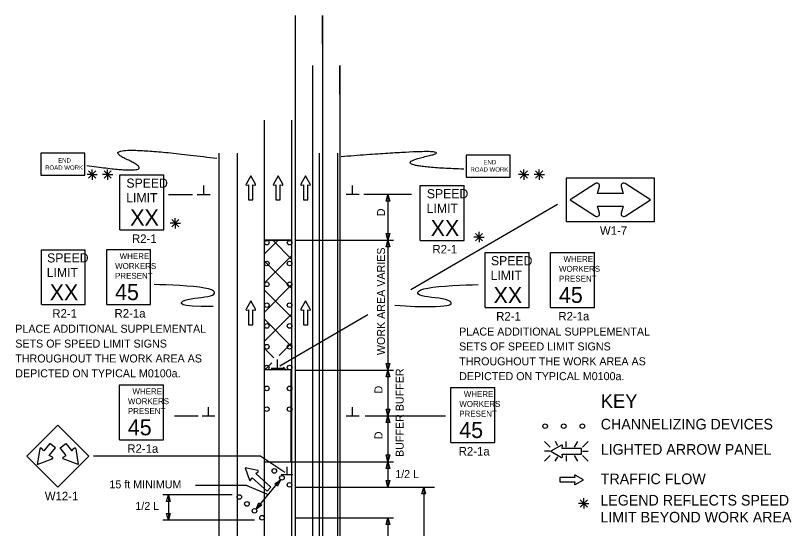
# Model space of a CAD drawing. Extents: x 16729 to 18482, y 7002 to 8333.
# Drawn here: x 16736 to 17415, y 7884 to 8333 of the extents above; entities that cross this region are included whole.
import ezdxf

# ---------------------------------------------------------------- set-up
doc = ezdxf.new("R2010")
doc.units = 0
for name, color, linetype in [('ALI_LEGAL_EX', 7, 'Continuous'), ('MT_SCRATCH_LEVEL_E', 7, 'Continuous'), ('PAVT_EDGE_EX', 7, 'Continuous'), ('TRAFFIC_SIGNS_PR', 7, 'Continuous'), ('TYPICAL_TEXT_DIMEN_EX', 7, 'Continuous'), ('TYPICAL_TEXT_DIMEN_PR', 7, 'Continuous')]:
    doc.layers.add(name, color=color, linetype=linetype)

msp = doc.modelspace()

# ---------------------------------------------------------------- linework, layer by layer
at = {"layer": 'ALI_LEGAL_EX'}
for p, q in [((16980.68, 8333.08), (16980.68, 7514.94)), ((17004.68, 8333.08), (17004.68, 7514.94)), ((16995.95, 8289.26), (16995.95, 7471.12)), ((17019.95, 8289.26), (17019.95, 7471.12)), ((16953.87, 7620.35), (16953.87, 8241.48)), ((16977.87, 7620.35), (16977.87, 8241.48))]:
    msp.add_line(p, q, dxfattribs=at)
for points in [[(17004.68, 8308.08), (17004.68, 8333.08)], [(17019.95, 8264.26), (17019.95, 8289.26)], [(16953.87, 8175.35), (16953.87, 8200.34)], [(16977.87, 8175.35), (16977.87, 8200.34)], [(16953.87, 8075.35), (16953.87, 8100.35)], [(16977.87, 8075.35), (16977.87, 8100.35)]]:
    msp.add_lwpolyline(points, dxfattribs=at)
at = {"layer": 'MT_SCRATCH_LEVEL_E'}
for p, q in [((16941.87, 8192.71), (16937.75, 8185.47)), ((16946.01, 8185.47), (16941.87, 8192.71)), ((16965.77, 8192.71), (16961.66, 8185.47)), ((16969.92, 8185.47), (16965.77, 8192.71)), ((16989.82, 8192.71), (16985.71, 8185.47)), ((16993.97, 8185.47), (16989.82, 8192.71)), ((16938.24, 8184.79), (16940.01, 8185.1)), ((16940.01, 8185.1), (16940.01, 8171.85)), ((16943.76, 8171.85), (16943.76, 8185.1)), ((16943.76, 8185.1), (16945.53, 8184.79)), ((16962.14, 8184.79), (16963.92, 8185.1)), ((16963.92, 8185.1), (16963.92, 8171.85)), ((16967.66, 8171.85), (16967.66, 8185.1)), ((16967.66, 8185.1), (16969.44, 8184.79)), ((16986.19, 8184.79), (16987.97, 8185.1)), ((16987.97, 8185.1), (16987.97, 8171.85)), ((16991.71, 8171.85), (16991.71, 8185.1)), ((16991.71, 8185.1), (16993.49, 8184.79)), ((16940.01, 8171.85), (16943.76, 8171.85)), ((16963.92, 8171.85), (16967.66, 8171.85)), ((16987.97, 8171.85), (16991.71, 8171.85)), ((16941.87, 8083.36), (16937.75, 8076.12)), ((16946.01, 8076.12), (16941.87, 8083.36)), ((16989.82, 8083.36), (16985.71, 8076.12)), ((16993.97, 8076.12), (16989.82, 8083.36)), ((16938.24, 8075.44), (16940.01, 8075.75)), ((16940.01, 8075.75), (16940.01, 8062.5)), ((16943.76, 8062.5), (16943.76, 8075.75)), ((16943.76, 8075.75), (16945.53, 8075.44)), ((16986.19, 8075.44), (16987.97, 8075.75)), ((16987.97, 8075.75), (16987.97, 8062.5)), ((16991.71, 8062.5), (16991.71, 8075.75)), ((16991.71, 8075.75), (16993.49, 8075.44)), ((16940.01, 8062.5), (16943.76, 8062.5)), ((16987.97, 8062.5), (16991.71, 8062.5)), ((16948, 7934.97), (16937.12, 7937.29)), ((16937.12, 7937.29), (16940.66, 7926.77)), ((16946.36, 7932.4), (16948.25, 7933.89)), ((16959.53, 7920.61), (16946.36, 7932.4)), ((17225.12, 7930.63), (17225.43, 7928.85)), ((17233.04, 7927), (17225.8, 7931.11)), ((16941.76, 7926.64), (16943.03, 7928.68)), ((16943.03, 7928.68), (16956.2, 7916.89)), ((17225.43, 7928.85), (17212.17, 7928.85)), ((17212.17, 7928.85), (17212.17, 7925.11)), ((17212.17, 7925.11), (17225.43, 7925.11)), ((17225.43, 7925.11), (17225.12, 7923.33)), ((17225.8, 7922.85), (17233.04, 7927)), ((16956.2, 7916.89), (16959.53, 7920.61))]:
    msp.add_line(p, q, dxfattribs=at)
for centre, radius, start, end in [((16938.16, 8185.25), 0.463, 150.42484, 279.96381), ((16945.6, 8185.25), 0.463, 260.03619, 29.77312), ((16962.07, 8185.25), 0.463, 150.42484, 279.96381), ((16969.51, 8185.25), 0.463, 260.03619, 29.77312), ((16986.12, 8185.25), 0.463, 150.42484, 279.96381), ((16993.56, 8185.25), 0.463, 260.03619, 29.77312), ((16938.16, 8075.9), 0.463, 150.42484, 279.96381), ((16945.6, 8075.9), 0.463, 260.03619, 29.77312), ((16986.12, 8075.9), 0.463, 150.42484, 279.96381), ((16993.56, 8075.9), 0.463, 260.03619, 29.77312), ((16947.86, 7934.37), 0.617, 308.20022, 77.93715), ((17225.58, 7930.7), 0.463, 60.42484, 189.96381), ((16941.24, 7926.97), 0.617, 198.58887, 328.12784), ((17225.58, 7923.26), 0.463, 170.03619, 299.77312)]:
    msp.add_arc(centre, radius, start, end, dxfattribs=at)
at = {"layer": 'PAVT_EDGE_EX'}
for p, q in [((16913.87, 8212.75), (16913.87, 7553.94)), ((16929.87, 8212.75), (16929.87, 7553.94)), ((17001.87, 8212.75), (17001.87, 7553.94)), ((17017.87, 8212.75), (17017.87, 7553.94)), ((16977.87, 8136.53), (16953.87, 8136.53)), ((16953.87, 8136.53), (16977.87, 8136.53)), ((16953.87, 8136.53), (16977.87, 8136.53)), ((16953.87, 8124.62), (16965.77, 8136.53)), ((16977.87, 8119.72), (16961.06, 8136.53)), ((16953.87, 8099.17), (16977.87, 8123.17)), ((16977.87, 8094.26), (16953.87, 8118.26)), ((16953.87, 8073.71), (16977.87, 8097.71)), ((16977.87, 8068.81), (16953.87, 8092.81)), ((16953.87, 8048.26), (16977.87, 8072.26)), ((16977.87, 8043.35), (16953.87, 8067.35)), ((16966.65, 8035.59), (16977.87, 8046.8)), ((16962.09, 8033.67), (16953.87, 8041.89)), ((16953.87, 8022.8), (16960.46, 8029.4)), ((16972.96, 8022.8), (16970.42, 8025.34))]:
    msp.add_line(p, q, dxfattribs=at)
msp.add_lwpolyline([(16977.33, 8023.14), (16953.49, 8023.14), (16953.49, 7942.8), (16977.33, 7942.8)], close=True, dxfattribs=at)
at = {"layer": 'TRAFFIC_SIGNS_PR'}
for p, q in [((16827.3, 8193.63), (16865.7, 8193.63)), ((16827.3, 8145.63), (16827.3, 8193.63)), ((16865.7, 8145.63), (16865.7, 8193.63)), ((17090.18, 8184.37), (17128.58, 8184.37)), ((17090.18, 8136.37), (17090.18, 8184.37)), ((17128.58, 8136.37), (17128.58, 8184.37)), ((16827.3, 8145.63), (16865.7, 8145.63)), ((17090.18, 8136.37), (17128.58, 8136.37)), ((16758.65, 8128.21), (16797.05, 8128.21)), ((16758.65, 8080.21), (16758.65, 8128.21)), ((16797.05, 8080.21), (16797.05, 8128.21)), ((16815.85, 8128.3), (16854.25, 8128.3)), ((16815.85, 8080.3), (16815.85, 8128.3)), ((16854.25, 8080.3), (16854.25, 8128.3)), ((17147.01, 8125.72), (17185.41, 8125.72)), ((17147.01, 8077.72), (17147.01, 8125.72)), ((17185.41, 8077.72), (17185.41, 8125.72)), ((17204.21, 8125.8), (17242.61, 8125.8)), ((17204.21, 8077.8), (17204.21, 8125.8)), ((17242.61, 8077.8), (17242.61, 8125.8)), ((16758.65, 8080.21), (16797.05, 8080.21)), ((16815.85, 8080.3), (16854.25, 8080.3)), ((17147.01, 8077.72), (17185.41, 8077.72)), ((17204.21, 8077.8), (17242.61, 8077.8)), ((16827.03, 8010.02), (16865.43, 8010.02)), ((16827.03, 7962.02), (16827.03, 8010.02)), ((16865.43, 7962.02), (16865.43, 8010.02)), ((17116.98, 8007.65), (17155.38, 8007.65)), ((17116.98, 7959.65), (17116.98, 8007.65)), ((17155.38, 7959.65), (17155.38, 8007.65)), ((16773.02, 7974.75), (16745.87, 7947.59)), ((16800.17, 7947.59), (16773.02, 7974.75)), ((16827.03, 7962.02), (16865.43, 7962.02)), ((17116.98, 7959.65), (17155.38, 7959.65)), ((17198.85, 7960.38), (17203.79, 7955.45)), ((17210.62, 7956.56), (17208.41, 7960.38)), ((17217.94, 7955.45), (17217.94, 7960.38)), ((17225.17, 7955.45), (17228.02, 7960.38)), ((17232.08, 7955.45), (17237.02, 7960.38)), ((16758.11, 7953.99), (16757.34, 7954.12)), ((17203.79, 7951.89), (17198.85, 7951.89)), ((17232.08, 7951.89), (17237.02, 7951.89)), ((16745.87, 7947.59), (16773.02, 7920.44)), ((16767.92, 7946.12), (16768.21, 7945.37)), ((16773.02, 7920.44), (16800.17, 7947.59)), ((17198.85, 7943.4), (17203.79, 7948.34)), ((17208.36, 7943.4), (17210.48, 7947.06)), ((17217.94, 7948.34), (17217.94, 7943.4)), ((17228.06, 7943.4), (17225.22, 7948.34)), ((17232.08, 7948.34), (17237.02, 7943.4))]:
    msp.add_line(p, q, dxfattribs=at)
for points in [[(16758.34, 8193.37), (16796.74, 8193.37), (16796.74, 8212.57), (16758.34, 8212.57)], [(17130.46, 8191.77), (17168.85, 8191.77), (17168.85, 8210.97), (17130.46, 8210.97)], [(17294.85, 8152.68), (17218.05, 8152.68), (17218.05, 8191.08), (17294.85, 8191.08)]]:
    msp.add_lwpolyline(points, close=True, dxfattribs=at)
for points in [[(17243.57, 8186.08), (17221.25, 8171.88), (17243.57, 8157.67)], [(17265.97, 8183.6), (17267.65, 8177.48), (17245.26, 8177.48), (17246.93, 8183.6)], [(17269.33, 8157.68), (17291.65, 8171.88), (17269.33, 8186.08)], [(17246.93, 8160.16), (17245.26, 8166.28), (17267.65, 8166.28), (17265.97, 8160.16)], [(16768.31, 7946.82), (16765.63, 7948.25), (16770.9, 7954.8), (16765.98, 7958.77), (16760.7, 7952.21), (16758.7, 7954.51)], [(16777.74, 7946.82), (16780.41, 7948.25), (16775.14, 7954.8), (16780.06, 7958.77), (16785.34, 7952.21), (16787.35, 7954.51)], [(17213.86, 7957.17), (17204.57, 7951.89), (17213.87, 7946.57)], [(16757.34, 7954.12), (16755.08, 7940.23), (16768.21, 7945.37)], [(16788.71, 7954.12), (16790.96, 7940.23), (16777.83, 7945.37)], [(17214.74, 7947.2), (17214.34, 7949.47), (17231.35, 7949.47), (17231.35, 7954.27), (17214.34, 7954.27), (17214.74, 7956.55)]]:
    msp.add_lwpolyline(points, dxfattribs=at)
for centre in [(16955.97, 8134.41), (16975.84, 8134.41), (16955.97, 8116.19), (16975.84, 8116.19), (16955.97, 8097.98), (16975.84, 8097.98), (16955.97, 8079.76), (16975.84, 8079.76), (16955.97, 8061.55), (16975.84, 8061.55), (16955.97, 8043.33), (16975.84, 8043.33), (16955.97, 8025.12), (16975.84, 8025.12), (16955.97, 8006.91), (16975.84, 8006.91), (16955.85, 7988.7), (16975.84, 7988.69), (17199.42, 7973.92), (17215.72, 7973.92), (17232.02, 7973.92), (16962.5, 7934.71), (16969.15, 7928.65), (16975.8, 7922.58), (16931.86, 7911.95), (16938.51, 7905.88), (16945.16, 7899.82), (16951.8, 7893.75), (16951.8, 7893.75)]:
    msp.add_circle(centre, 2, dxfattribs=at)
for centre, radius, start, end in [((17244.77, 8184.19), 2.24, 344.67308, 122.46963), ((17268.13, 8184.19), 2.24, 57.53038, 195.32692), ((17244.77, 8159.57), 2.24, 237.53038, 15.32692), ((17268.13, 8159.57), 2.24, 164.69282, 302.45235), ((17214.15, 7956.65), 0.598, 350.73078, 118.89165), ((16758.11, 7953.98), 0.786, 41.8659, 170.0393), ((16787.93, 7953.98), 0.786, 9.9607, 138.1341), ((16767.92, 7946.12), 0.8, 291.40774, 61.17916), ((16778.12, 7946.12), 0.8, 118.82084, 248.59226), ((17214.15, 7947.1), 0.597, 241.48329, 9.95933)]:
    msp.add_arc(centre, radius, start, end, dxfattribs=at)
for points in [[(16798.34, 8201.97), (16866.67, 8191.88), (16799.95, 8222.7), (16912.21, 8208.18)], [(17128.36, 8198.71), (17056.34, 8201), (17132.86, 8218.41), (17020.93, 8209.49)]]:
    msp.add_open_spline(points, degree=2, dxfattribs=at)
at = {"layer": 'TYPICAL_TEXT_DIMEN_PR'}
for p, q in [((16799.98, 8197.15), (16806.35, 8190.77)), ((16806.35, 8197.15), (16799.98, 8190.77)), ((16803.16, 8193.96), (16803.16, 8198.41)), ((16813.48, 8197.15), (16819.86, 8190.77)), ((16819.86, 8197.15), (16813.48, 8190.77)), ((16816.67, 8193.96), (16816.67, 8198.41)), ((17183.98, 8197.08), (17177.6, 8190.7)), ((17177.61, 8197.08), (17183.98, 8190.7)), ((17180.79, 8193.89), (17180.79, 8198.35)), ((17191.11, 8197.08), (17197.49, 8190.7)), ((17197.49, 8197.08), (17191.11, 8190.7)), ((17194.3, 8193.89), (17194.3, 8198.35)), ((16803.16, 8193.96), (16798.63, 8193.96)), ((16803.16, 8193.96), (16806.35, 8193.96)), ((16803.16, 8193.96), (16807.64, 8193.96)), ((16803.16, 8193.96), (16803.16, 8189.46)), ((16816.67, 8193.96), (16812.14, 8193.96)), ((16816.67, 8193.96), (16819.86, 8193.96)), ((16816.67, 8193.96), (16821.15, 8193.96)), ((16816.67, 8193.96), (16816.67, 8189.46)), ((17180.79, 8193.89), (17176.26, 8193.89)), ((17180.79, 8193.89), (17183.98, 8193.89)), ((17180.79, 8193.89), (17185.27, 8193.89)), ((17180.79, 8193.89), (17180.79, 8189.39)), ((17194.3, 8193.89), (17189.77, 8193.89)), ((17194.3, 8193.89), (17197.49, 8193.89)), ((17194.3, 8193.89), (17198.78, 8193.89)), ((17194.3, 8193.89), (17194.3, 8189.39)), ((16900.74, 8176.53), (16900.74, 8184.31)), ((16900.74, 8176.53), (16900.74, 8184.31)), ((17030.99, 8176.53), (17030.99, 8184.31)), ((16869.89, 8176.53), (16890.87, 8176.53)), ((16878.29, 8176.53), (16890.87, 8176.53)), ((16895.12, 8176.53), (16906.37, 8176.53)), ((16895.12, 8176.53), (16906.37, 8176.53)), ((17036.62, 8176.53), (17025.37, 8176.53)), ((17082.51, 8176.53), (17040.87, 8176.53)), ((17060.3, 8170.66), (17061.87, 8176.53)), ((17061.87, 8176.53), (17063.44, 8170.66)), ((17061.87, 8176.53), (17061.87, 8136.53)), ((17061.87, 8170.66), (17060.3, 8170.66)), ((17063.44, 8170.66), (17061.87, 8170.66)), ((17081.82, 8093.32), (17210.29, 8168.01)), ((16872.69, 8154.61), (16879.06, 8148.23)), ((16879.06, 8154.61), (16872.69, 8148.23)), ((16875.87, 8151.42), (16875.87, 8155.88)), ((16875.87, 8151.42), (16871.34, 8151.42)), ((16875.87, 8151.42), (16879.06, 8151.42)), ((16875.87, 8151.42), (16880.35, 8151.42)), ((16875.87, 8151.42), (16875.87, 8146.92)), ((17061.87, 8136.53), (17060.3, 8142.39)), ((17060.3, 8142.39), (17061.87, 8142.39)), ((17061.87, 8142.39), (17063.44, 8142.39)), ((17063.44, 8142.39), (17061.87, 8136.53)), ((17138.4, 8142.47), (17144.78, 8136.09)), ((17144.78, 8142.47), (17138.4, 8136.09)), ((17141.59, 8139.28), (17141.59, 8143.74)), ((16980.8, 8136.53), (17066.87, 8136.53)), ((17060.3, 8130.66), (17061.87, 8136.53)), ((17061.87, 8136.53), (17061.87, 8022.8)), ((17061.87, 8136.53), (17063.44, 8130.66)), ((17141.59, 8139.28), (17137.06, 8139.28)), ((17141.59, 8139.28), (17144.78, 8139.28)), ((17141.59, 8139.28), (17146.07, 8139.28)), ((17141.59, 8139.28), (17141.59, 8134.78)), ((17061.87, 8130.66), (17060.3, 8130.66)), ((17063.44, 8130.66), (17061.87, 8130.66)), ((16967.39, 8026.78), (17044.25, 8071.47)), ((16965.27, 8024.49), (16965.27, 8032.27)), ((17061.87, 8022.8), (17060.3, 8028.66)), ((17060.3, 8028.66), (17061.87, 8028.66)), ((17061.87, 8028.66), (17063.44, 8028.66)), ((17063.44, 8028.66), (17061.87, 8022.8)), ((16959.65, 8024.49), (16970.9, 8024.49)), ((16980.42, 8022.8), (17066.87, 8022.8)), ((17060.3, 8016.94), (17061.87, 8022.8)), ((17061.87, 8022.8), (17061.87, 7982.8)), ((17061.87, 8022.8), (17063.44, 8016.94)), ((17061.87, 8016.94), (17060.3, 8016.94)), ((17063.44, 8016.94), (17061.87, 8016.94)), ((17061.87, 7997.82), (17061.87, 7994.22)), ((16904.85, 7982.59), (16904.85, 7990.37)), ((17030.99, 7982.59), (17030.99, 7990.37)), ((17061.87, 7982.8), (17060.3, 7988.66)), ((17060.3, 7988.66), (17061.87, 7988.66)), ((17061.87, 7988.66), (17063.44, 7988.66)), ((17063.44, 7988.66), (17061.87, 7982.8)), ((16875.14, 7982.8), (16895.79, 7982.8)), ((16910.48, 7982.59), (16899.23, 7982.59)), ((17036.62, 7982.59), (17025.37, 7982.59)), ((17041.96, 7982.8), (17112.26, 7982.8)), ((17060.3, 7976.94), (17061.87, 7982.8)), ((17061.87, 7982.8), (17061.87, 7942.8)), ((17061.87, 7982.8), (17063.44, 7976.94)), ((17061.87, 7976.94), (17060.3, 7976.94)), ((17063.44, 7976.94), (17061.87, 7976.94)), ((17061.87, 7957.82), (17061.87, 7954.22)), ((16950.82, 7947.75), (16804.26, 7947.75)), ((16950.82, 7947.75), (16971.74, 7933.71)), ((17061.87, 7942.8), (17060.3, 7948.66)), ((17060.3, 7948.66), (17061.87, 7948.66)), ((17061.87, 7948.66), (17063.44, 7948.66)), ((17063.44, 7948.66), (17061.87, 7942.8)), ((16973.69, 7931.21), (16973.69, 7938.22)), ((16977.87, 7942.8), (17066.87, 7942.8)), ((17060.3, 7936.94), (17061.87, 7942.8)), ((17061.87, 7936.94), (17060.3, 7936.94)), ((17061.87, 7942.8), (17061.87, 7920.56)), ((17061.87, 7942.8), (17063.44, 7936.94)), ((17063.44, 7936.94), (17061.87, 7936.94)), ((16978.76, 7931.21), (16968.63, 7931.21)), ((16946.52, 7901.28), (16967.96, 7927.04)), ((16963.01, 7923.54), (16967.96, 7927.04)), ((16964.21, 7922.53), (16963.01, 7923.54)), ((16967.96, 7927.04), (16965.42, 7921.53)), ((17061.87, 7920.56), (17060.3, 7926.42)), ((17060.3, 7926.42), (17061.87, 7926.42)), ((17061.87, 7926.42), (17063.44, 7926.42)), ((17063.44, 7926.42), (17061.87, 7920.56)), ((16938.38, 7921.87), (16893.52, 7921.87)), ((16938.38, 7921.87), (16957.12, 7914.01)), ((16965.42, 7921.53), (16964.21, 7922.53)), ((16980.8, 7920.56), (17102.73, 7920.56)), ((17091.61, 7914.69), (17093.18, 7920.56)), ((17093.18, 7920.56), (17093.18, 7802.68)), ((17093.18, 7920.56), (17094.75, 7914.69)), ((16925.69, 7913.72), (16864.87, 7913.72)), ((16868.3, 7907.86), (16869.87, 7913.72)), ((16869.87, 7913.72), (16871.44, 7907.86)), ((16869.87, 7913.72), (16869.87, 7891.75)), ((17093.18, 7914.69), (17091.61, 7914.69)), ((17094.75, 7914.69), (17093.18, 7914.69)), ((17230.05, 7909.51), (17236.42, 7903.14)), ((17236.42, 7909.51), (17230.05, 7903.14)), ((17233.23, 7906.32), (17233.23, 7910.78)), ((16869.87, 7907.86), (16868.3, 7907.86)), ((16871.44, 7907.86), (16869.87, 7907.86)), ((16946.52, 7901.28), (16949.06, 7906.79)), ((16951.48, 7904.78), (16946.52, 7901.28)), ((16949.06, 7906.79), (16950.27, 7905.78)), ((16950.27, 7905.78), (16951.48, 7904.78)), ((17233.23, 7906.32), (17228.7, 7906.32)), ((17233.23, 7906.32), (17236.42, 7906.32)), ((17233.23, 7906.32), (17237.71, 7906.32)), ((17233.23, 7906.32), (17233.23, 7901.82)), ((16869.87, 7891.75), (16868.3, 7897.61)), ((16868.3, 7897.61), (16869.87, 7897.61)), ((16869.87, 7897.61), (16871.44, 7897.61)), ((16871.44, 7897.61), (16869.87, 7891.75)), ((16945.24, 7891.75), (16864.87, 7891.75)), ((16980.8, 7893.75), (17066.87, 7893.75)), ((17060.3, 7887.89), (17061.87, 7893.75)), ((17061.87, 7893.75), (17061.87, 7853.75)), ((17061.87, 7893.75), (17063.44, 7887.89)), ((17061.87, 7887.89), (17060.3, 7887.89)), ((17063.44, 7887.89), (17061.87, 7887.89))]:
    msp.add_line(p, q, dxfattribs=at)
for points, degree in [([(16908.98, 8078.54), (16877.42, 8077.59), (16879.57, 8086.24), (16912.09, 8086.24), (16912.09, 8095.9), (16869.23, 8097.42), (16857.32, 8097.68)], 3), ([(17068.08, 8079.61), (17120.93, 8076.11), (17120.26, 8086.24), (17086.03, 8086.24), (17086.03, 8095.9), (17128.89, 8097.42), (17140.8, 8097.68)], 3), ([(17326.18, 7906.91), (17326.2, 7906.91), (17326.21, 7906.91), (17326.21, 7906.91)], 2)]:
    msp.add_open_spline(points, degree=degree, dxfattribs=at)

# ---------------------------------------------------------------- texts
at = {"layer": 'TRAFFIC_SIGNS_PR'}
for s, height, p in [('END', 3.831, (16773.34, 8204.5)), ('ROAD WORK', 3.831, (16761.95, 8198.12)), ('END', 3.831, (17145.46, 8202.9)), ('ROAD WORK', 3.831, (17134.06, 8196.51)), ('SPEED', 8, (16833.07, 8182.49)), ('SPEED', 8, (17095.95, 8173.23)), ('LIMIT', 8, (16832.91, 8169.69)), ('LIMIT', 8, (17095.79, 8160.43)), ('XX', 14.031, (16836.41, 8149.39)), ('XX', 14.031, (17099.29, 8140.13)), ('W1-7', 7.44, (17247.41, 8141.24)), ('R2-1', 7.44, (16837.98, 8134.19)), ('R2-1', 7.44, (17100.86, 8124.93)), ('SPEED', 8, (16763.68, 8117.07)), ('WHERE', 5.2, (16827.16, 8119.98)), ('SPEED', 8, (17152.05, 8114.58)), ('WHERE', 5.2, (17215.52, 8117.49)), ('WORKERS', 5.2, (16823.23, 8111.38)), ('WORKERS', 5.2, (17211.59, 8108.89)), ('LIMIT', 8, (16763.35, 8104.27)), ('PRESENT', 5.2, (16823.16, 8102.78)), ('LIMIT', 8, (17151.71, 8101.78)), ('PRESENT', 5.2, (17211.52, 8100.29)), ('XX', 14.031, (16765.96, 8083.97)), ('45', 14.031, (16823.15, 8084.15)), ('XX', 14.031, (17154.32, 8081.47)), ('45', 14.031, (17211.52, 8081.66)), ('R2-1', 7.44, (16768.26, 8068.77)), ('R2-1a', 7.44, (16822.7, 8068.86)), ('R2-1', 7.44, (17156.62, 8066.28)), ('R2-1a', 7.44, (17211.06, 8066.36)), ('PLACE ADDITIONAL SUPPLEMENTAL', 7, (16735.85, 8055.6)), ('PLACE ADDITIONAL SUPPLEMENTAL', 7, (17124.21, 8053.11)), ('SETS OF SPEED LIMIT SIGNS', 7, (16735.85, 8042.6)), ('SETS OF SPEED LIMIT SIGNS', 7, (17124.21, 8040.11)), ('THROUGHOUT THE WORK AREA AS', 7, (16735.85, 8029.6)), ('THROUGHOUT THE WORK AREA AS', 7, (17124.21, 8027.11)), ('DEPICTED ON TYPICAL M0100a.', 7, (16735.85, 8016.6)), ('DEPICTED ON TYPICAL M0100a.', 7, (17124.21, 8014.11)), ('WHERE', 5.2, (16838.34, 8001.71)), ('WORKERS', 5.2, (16834.41, 7993.11)), ('WHERE', 5.2, (17128.29, 7999.33)), ('WORKERS', 5.2, (17124.36, 7990.73)), ('PRESENT', 5.2, (16834.34, 7984.51)), ('PRESENT', 5.2, (17124.29, 7982.13)), ('45', 14.031, (16834.33, 7965.88)), ('45', 14.031, (17124.29, 7963.5)), ('R2-1a', 7.44, (16833.88, 7950.58)), ('R2-1a', 7.44, (17123.83, 7948.21)), ('W12-1', 7.44, (16761.7, 7909))]:
    msp.add_text(s, height=height, dxfattribs=at).set_placement(p)
at = {"layer": 'TYPICAL_TEXT_DIMEN_EX'}
for s, height, p in [('KEY', 12, (17248.11, 7989.85)), ('CHANNELIZING DEVICES', 9.3, (17248.11, 7970.98)), ('LIGHTED ARROW PANEL', 9.3, (17248.11, 7948.93)), ('TRAFFIC FLOW', 9.3, (17248.11, 7923.13)), ('LEGEND REFLECTS SPEED', 9.3, (17247.79, 7904.43)), ('LIMIT BEYOND WORK AREA', 9.3, (17247.79, 7889.63))]:
    msp.add_text(s, height=height, dxfattribs=at).set_placement(p)
at = {"layer": 'TYPICAL_TEXT_DIMEN_PR'}
for s, p in [('D', (17059.31, 8157.5)), ('WORK AREA VARIES', (17059.31, 8036.02)), ('BUFFER', (17075.68, 7986.95)), ('D', (17057.13, 8002.45)), ('BUFFER', (17075.68, 7946.95)), ('D', (17057.13, 7962.45))]:
    msp.add_text(s, height=7, rotation=90, dxfattribs=at).set_placement(p)
for s, p in [('1/2 L', (17068.27, 7928.47)), ('15 ft MINIMUM', (16818.23, 7919.5)), ('1/2 L', (16840.94, 7900.57))]:
    msp.add_text(s, height=7, dxfattribs=at).set_placement(p)

doc.saveas('drawing.dxf')
